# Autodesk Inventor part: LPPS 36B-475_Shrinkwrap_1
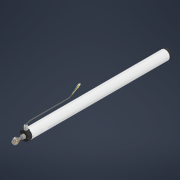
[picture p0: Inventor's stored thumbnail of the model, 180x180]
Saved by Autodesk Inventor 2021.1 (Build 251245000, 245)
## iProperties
Created: 2020-09
Part Number: LPPS 36B-475_Shrinkwrap_1
Material: Generic
Document SubType Name: Modeling
Designer: J. Nielson
Density: 1 g/cm^3
Appearance: Default
Author: J. Nielson
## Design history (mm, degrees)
derived "LPPS 36B-475.iam"
body "Solid1"
node "LPPS 36B Cable End Cap.iam:1::LPPS-36B PLASTIC CABLE END.ipt"
node "LPPS 36B Cable End Cap.iam:1::LPPS 36B- Cable Gland.ipt:1"
body "Solid2"
node "LPPS 36B Cable End Cap.iam:1::Cable Gland Cap.ipt:1"
body "Solid3"
node "LPPS 36B Cable End Cap.iam:1::Cable.ipt:1"
body "Solid4"
node "LPPS 36B Cable End Cap.iam:1::Cable Gland 2 of 2.ipt:1"
body "Solid5"
node "LPPS 36B Cable End Cap.iam:1::#6 Terminal Ring 22 - 18 AWG.i"
body "Solid6"
node "LPPS-36B-475 METAL HOUSING.ipt:1"
body "Solid7"
node "MALE Rod Eye SW.ipt:1"
body "Solid8"
node "LPPS-36B PLASTIC STROKE END.ipt:1"
body "Solid9"
node "LPPS 36B-475 Front Stop.ipt:1"
body "Solid10"
node "AS 1427 - M3 x 16.ipt:1"
body "Solid11"
node "AS 1427 - M3 x 16.ipt:2"
body "Solid12"
node "AS 1427 - M3 x 16.ipt:3"
body "Solid13"
node "AS 1427 - M3 x 16.ipt:4"
body "Solid14"
node "AS 1112 - M8  Type 5.ipt:1"
body "Solid15"
node "AS 1968 - 1976 - 8.ipt:1"
body "Solid16"
node "AS 1237 - 8.ipt:1"
body "Solid17"
